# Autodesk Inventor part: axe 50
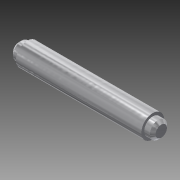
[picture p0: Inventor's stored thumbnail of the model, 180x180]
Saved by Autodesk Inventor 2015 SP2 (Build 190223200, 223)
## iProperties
Created: 2015-08
Part Number: axe 50
Material: Générique
Document SubType Name: Modeling
Designer: Dominique
Density: 1 g/cm^3
Appearance: Usiné - Aluminium
Author: Dominique
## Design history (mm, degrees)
sketch "Esquisse1"
  geometry: L1 (0, 0)-(50, 0); L2 (50, 0)-(50, 3); L3 (47, 4)-(3, 4); L4 (0, 3)-(0, 0); L5 (3, 4)-(3, 3); L6 (3, 3)-(0, 3); L7 (47, 4)-(47, 3); L8 (47, 3)-(50, 3)
  constraints: 16 end point, 2 parallel, 1 horizontal, 1 perpendicular
  dimensions: "d10" = 3 distance between parallel lines of L5 L4; "d11" = 3 distance between parallel lines of L2 L7; "d12" = 50 distance between parallel lines of L4 L2
revolve "Révolution1" sketch "Esquisse1" stored, may be unused: angle "d6" = 90 deg
chamfer "Chanfrein1" distance "d7" = 1; stored, may be unused: second distance "d8" = 2, angle "d9" = 45 deg
node "Solide1"
